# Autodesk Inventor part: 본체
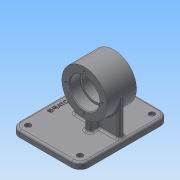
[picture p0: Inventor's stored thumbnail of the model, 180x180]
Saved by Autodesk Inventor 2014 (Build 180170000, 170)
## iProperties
Created: 2019-09
Part Number: 본체
Material: 일반
Document SubType Name: Modeling
Designer: net
Density: 1 g/cm^3
Appearance: 기본값
Mass: 205.321 g
Surface Area: 496.535 cm^2
Volume: 205.321 cm^3
Author: net
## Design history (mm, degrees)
sketch "스케치1"
  geometry: L1 (-21, 32)-(21, 32); L2 (21, 32)-(21, 0); L3 (21, 0)-(-21, 0); L4 (-21, 0)-(-21, 32); L5 (-21, 0)-(-6, 0); L6 (-6, 0)-(-6, 21); L7 (-6, 21)-(-21, 21); L8 (-21, 21)-(-21, 0); L9 (-6, 0)-(6, 0); L10 (6, 0)-(6, 18); L11 (6, 18)-(-6, 18); L12 (-6, 18)-(-6, 0); L13 (6, 0)-(21, 0); L14 (21, 0)-(21, 21); L15 (21, 21)-(6, 21); L16 (6, 21)-(6, 0); 2 further points
  constraints: 32 end point, 8 parallel, 4 horizontal, 4 perpendicular, 2 midpoint, 1 coincident, 1 point on line
  dimensions: "d0" = 42 distance between parallel lines of L2 L4; "d1" = 15 distance of L6.end L7.end; "d2" = 15 distance of L14.end L15.end (= d1); "d3" = 64 diameter of L1 L13; "d4" = 42 diameter of L15 L3; "d5" = 42 diameter of L7 L5; "d6" = 36 diameter of L11 L3
revolve "회전1" sketch "스케치1" stored, may be unused: angle "d7" = 90 deg
sketch "스케치2" dims "d8" = 52
  geometry: C1 r 21 at (0, 0) reference; C2 r 32 at (0, 0) reference; 2 further points
  constraints: 2 vertical alignment, 1 coincident, 2 other
hole "구멍1" sketch "스케치2" at (0, 26) diameter "d9" = 3.242; stored, may be unused: countersink angle "d13" = 90 deg, drill point angle "d15" = 118 deg; dims "d10" = 8, "d11" = 4, "d12" = 2, "d14" = 10
chamfer "모따기1" distance "d19" = 1; stored, may be unused: second distance "d20" = 2, angle "d21" = 45 deg
fillet "모깎기1" dims "d22" = 0.3
node "작업 평면1"
sketch "스케치4"
  geometry: L1 (-4, -17)-(4, -17); L2 (4, -17)-(4, 17); L3 (4, 17)-(-4, 17); L4 (-4, 17)-(-4, -17); L5 (-4, -17)-(4, 17); L6 (4, -17)-(-4, 17); L7 (-32, -4)-(32, -4); L8 (32, -4)-(32, 4); L9 (32, 4)-(-32, 4); L10 (-32, 4)-(-32, -4); L11 (-32, -4)-(32, 4); L12 (32, -4)-(-32, 4); 1 further point
  constraints: 24 end point, 4 midpoint, 4 parallel, 2 horizontal, 2 perpendicular
  dimensions: "d26" = 8 distance of L2.end L3.end; "d27" = 8 distance of L9.end L7.start; "d28" = 64 distance of L8.end L9.end; "d29" = 34 distance of L3.end L1.start
extrude "돌출1" join sketch "스케치4" stored distance "d30" = 10; taper "d31" = 0 deg
sketch "스케치5"
  geometry: L1 (-62, -63)-(36, -63); L2 (36, -63)-(36, 63); L3 (36, 63)-(-62, 63); L4 (-62, 63)-(-62, -63); L5 (-62, -63)-(36, 63); L6 (36, -63)-(-62, 63); 3 further points
  constraints: 12 end point, 3 midpoint, 2 parallel, 1 horizontal, 1 horizontal alignment, 1 perpendicular
  dimensions: "d32" = 98 distance of L2.end L3.end; "d33" = 126 distance of L3.end L1.start; "d34" = 62 distance from line of L4 point (0, 0)
extrude "돌출2" join sketch "스케치5" distance "d35" = 9; taper "d36" = 0 deg
fillet "모깎기2" dims "d37" = 12
sketch "스케치6"
  geometry: A1 r 12 centre (-50, 51) between (-50, 63) and (-62, 51) reference; A2 r 12 centre (-50, -51) between (-62, -51) and (-50, -63) reference; A3 r 12 centre (24, -51) between (24, -63) and (36, -51) reference; A4 r 12 centre (24, 51) between (36, 51) and (24, 63) reference; 1 further point
hole "구멍2" sketch "스케치6" at (24, -51), (-50, -51), (24, 51), (-50, 51) diameter "d40" = 4.5; stored, may be unused: countersink angle "d44" = 90 deg, drill point angle "d46" = 118 deg; dims "d41" = 8, "d42" = 8, "d43" = 4.4, "d45" = 10
fillet "모깎기5" dims "d47" = 3
sketch "스케치7"
  geometry: L1 (-62, 51)-(-62, -51) reference; L2 (24, 63)-(-50, 63) reference; 2 further points
  constraints: 1 other
  dimensions: "d48" = 10 distance from line of L1 point (-52, 0); "d49" = 63 distance from line of L2 point (-52, 0)
feature "엠보싱1" sketch "스케치7" dims "d0" = 42, "d1" = 15, "d2" = 15 (= d1), "d3" = 64, "d4" = 42, "d5" = 42, "d6" = 36, "d8" = 52, "d50" = 0.5, "d51" = 0
fillet "모깎기6" dims "d52" = 3
fillet "모깎기7" dims "d53" = 3
node "솔리드1"
pattern_circular "원형 패턴1" dims angle "d17" = 360 deg
mirror "대칭1"
other parameters: "d23" = -59
